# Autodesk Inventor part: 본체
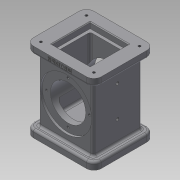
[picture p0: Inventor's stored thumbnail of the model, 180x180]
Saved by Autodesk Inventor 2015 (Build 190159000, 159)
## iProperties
Created: 2017-08
Part Number: 본체
Material: 일반
Document SubType Name: Modeling
Designer: Administrator
Density: 1 g/cm^3
Appearance: 기본값
Author: Administrator
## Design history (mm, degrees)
sketch "스케치1"
  geometry: L1 (37, -33)-(-37, -33); L2 (-37, -33)-(-37, 33); L3 (-37, 33)-(37, 33); L4 (37, 33)-(37, -33); L5 (37, -33)-(-37, 33); L6 (-37, -33)-(37, 33); 1 further point
  constraints: 12 end point, 2 midpoint, 2 parallel, 1 horizontal, 1 perpendicular
  dimensions: "d0" = 74 distance of L1.start L1.end; "d1" = 66 distance of L1.end L2.end
extrude "돌출1" new body sketch "스케치1" stored distance "d2" = 108; taper "d3" = 0 deg
sketch "스케치2"
  geometry: L1 (-46, -41)-(46, -41); L2 (46, -41)-(46, 41); L3 (46, 41)-(-46, 41); L4 (-46, 41)-(-46, -41); L5 (-46, -41)-(46, 41); L6 (46, -41)-(-46, 41); 1 further point
  constraints: 12 end point, 2 midpoint, 2 parallel, 1 horizontal, 1 perpendicular
  dimensions: "d4" = 92 distance of L2.end L3.end; "d5" = 82 distance of L1.end L2.end
extrude "돌출2" join sketch "스케치2" distance "d6" = 10; taper "d7" = 0 deg
fillet "모깎기1" dims "d8" = 10
fillet "모깎기2" dims "d9" = 10
fillet "모깎기3" dims "d10" = 3
sketch "스케치3"
  geometry: L1 (24, 24)-(-24, 24); L2 (-24, 24)-(-24, -24); L3 (-24, -24)-(24, -24); L4 (24, -24)-(24, 24); L5 (24, 24)-(-24, -24); L6 (-24, 24)-(24, -24); 1 further point
  constraints: 12 end point, 2 midpoint, 2 parallel, 1 horizontal, 1 perpendicular
  dimensions: "d12" = 48 distance of L2.end L3.end; "d13" = 48 distance of L3.end L1.start
extrude "돌출3" cut sketch "스케치3" distance "d14" = 16; taper "d15" = 0 deg
fillet "모깎기5" dims "d16" = 3
fillet "모깎기6" dims "d17" = 3
sketch "스케치4"
  geometry: L1 (-26, 26)-(26, 26); L2 (26, 26)-(26, -26); L3 (26, -26)-(-26, -26); L4 (-26, -26)-(-26, 26); L5 (-26, 26)-(26, -26); L6 (26, 26)-(-26, -26); 1 further point
  constraints: 12 end point, 2 midpoint, 2 parallel, 1 horizontal, 1 perpendicular
  dimensions: "d18" = 52 distance of L1.end L2.end; "d19" = 52 distance of L2.end L3.end
extrude "돌출4" cut sketch "스케치4" distance "d20" = 8; taper "d21" = 0 deg
sketch "스케치9"
  geometry: L1 (-22, -22)-(22, -22); L2 (22, -22)-(22, 22); L3 (22, 22)-(-22, 22); L4 (-22, 22)-(-22, -22); L5 (-22, -22)-(22, 22); L6 (22, -22)-(-22, 22); 1 further point
  constraints: 12 end point, 2 midpoint, 2 parallel, 1 horizontal, 1 perpendicular
  dimensions: "d35" = 44 distance of L2.end L3.end; "d36" = 44 distance of L3.end L1.start
extrude "돌출9" cut sketch "스케치9" distance "d37" = 74; taper "d38" = 0 deg
fillet "모깎기7" dims "d39" = 3
fillet "모깎기9" dims "d41" = 3
chamfer "모따기1" distance "d42" = 1; stored, may be unused: second distance "d43" = 2, angle "d44" = 45 deg
fillet "모깎기10" dims "d45" = 3
sketch "스케치10"
  geometry: C1 r 35 at (34, -41); 1 further point
  constraints: 1 centre point, 1 coincident
  dimensions: "d46" = 70 diameter of C1
extrude "돌출10" cut sketch "스케치10" distance "d47" = 3; taper "d48" = 0 deg
sketch "스케치11"
  geometry: C1 r 35 at (34, -41); 1 further point
  constraints: 1 centre point, 1 coincident
  dimensions: "d49" = 70 diameter of C1
extrude "돌출11" cut sketch "스케치11" distance "d50" = 3; taper "d51" = 0 deg
sketch "스케치12"
  geometry: C1 r 24 at (0, 0); 1 further point
  constraints: 1 centre point, 1 coincident
  dimensions: "d52" = 48 diameter of C1
extrude "돌출12" cut sketch "스케치12" stored distance "d53" = 123.5; taper "d54" = 0 deg
sketch "스케치13"
  geometry: L1 (46, -31)-(46, 31) reference; L2 (36, 41)-(-36, 41) reference; L3 (-46, 31)-(-46, -31) reference; L4 (-36, -41)-(36, -41) reference; L5 (-27, 27)-(-27, -27) reference; L6 (27, 27)-(-27, 27) reference; L7 (27, -27)-(27, 27) reference; L8 (-27, -27)-(27, -27) reference; A1 r 10 centre (36, -31) between (36, -41) and (46, -31) reference; A2 r 10 centre (36, 31) between (46, 31) and (36, 41) reference; A3 r 10 centre (-36, 31) between (-36, 41) and (-46, 31) reference; A4 r 10 centre (-36, -31) between (-46, -31) and (-36, -41) reference; 2 further points
  constraints: 1 coincident
hole "구멍1" sketch "스케치13" at (-36, 31) diameter "d55" = 3.242; stored, may be unused: countersink angle "d59" = 90 deg, drill point angle "d61" = 118 deg; dims "d56" = 4, "d57" = 4, "d58" = 2, "d60" = 6
sketch "스케치14" dims "d68" = 58
  geometry: 3 further points
  constraints: 2 vertical alignment, 1 coincident, 2 other
hole "구멍2" sketch "스케치14" at (0, 29) diameter "d69" = 3.242; stored, may be unused: countersink angle "d73" = 90 deg, drill point angle "d75" = 118 deg; dims "d70" = 4, "d71" = 4, "d72" = 2, "d74" = 6
sketch "스케치15"
  geometry: L1 (30, 104.477)-(30, 41); L2 (71, -13)-(61, -13) reference; 2 further points
  constraints: 2 end point, 1 point on line, 1 vertical, 1 vertical alignment
  dimensions: "d79" = 38 distance from line of L2 point (30, 25); "d80" = 42 distance of point (30, 67) point (30, 25)
hole "구멍3" sketch "스케치15" at (30, 67), (30, 25) diameter "d81" = 4.134; stored, may be unused: countersink angle "d85" = 90 deg, drill point angle "d87" = 118 deg; dims "d82" = 36.7, "d83" = 4, "d84" = 2, "d86" = 36.7
sketch "스케치16"
  geometry: L1 (82, -7)-(72, -7) reference; L2 (82, -7)-(82, 0) reference; L3 (82, 0)-(72, 0) reference; L4 (72, 0)-(72, -7) reference; 2 further points
  constraints: 1 vertical alignment, 1 other
  dimensions: "d88" = 4 vertical distance of point (36, -4) L2.end
feature "엠보싱1" sketch "스케치16" dims "d0" = 74, "d1" = 66, "d89" = 0.5, "d90" = 0
node "솔리드1"
mirror "대칭1"
pattern_linear "직사각형 패턴1" dims "d64" = 62, "d67" = 72
mirror "대칭2"
pattern_circular "원형 패턴1" dims angle "d77" = 360 deg
mirror "대칭3"
node "투영된 루프1"
node "투영된 루프2"
